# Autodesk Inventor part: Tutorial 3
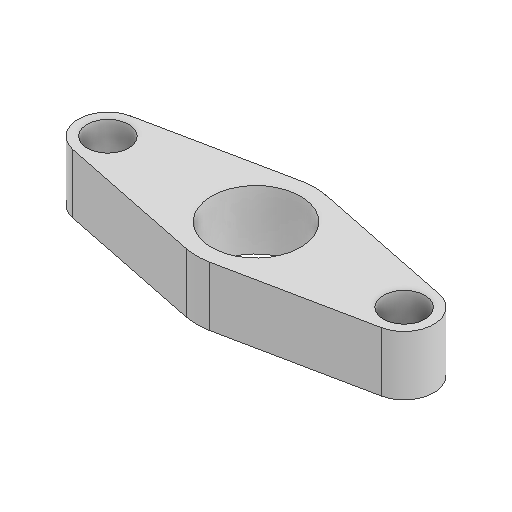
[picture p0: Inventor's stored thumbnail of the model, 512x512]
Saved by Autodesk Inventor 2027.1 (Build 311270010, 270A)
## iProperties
Created: 2021-04
Part Number: Tutorial 3
Material: Generic
Document SubType Name: Modeling
Designer: ASUS Laptop
Density: 1 g/cm^3
Appearance: Default
Author: ASUS Laptop
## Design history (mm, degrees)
sketch "Sketch1"
  geometry: L1 (26, -4.899)-(2, -9.798); L2 (-26, -4.899)-(-2, -9.798); L3 (-26, 4.899)-(-2, 9.798); L4 (26, 4.899)-(2, 9.798); L5 (0, 0)-(-33.69, 0); L6 (0, 0)-(0, -33.352); C1 r 7.5 at (0, 0); C2 r 3.5 at (25, 0); C3 r 3.5 at (-25, 0); A1 r 5 centre (-25, 0) between (-26, 4.899) and (-26, -4.899); A2 r 5 centre (25, 0) between (26, -4.899) and (26, 4.899); A3 r 10 centre (0, 0) between (-2, -9.798) and (2, -9.798); A4 r 10 centre (0, 0) between (2, 9.798) and (-2, 9.798); 1 further point
  constraints: 12 end point, 8 point on circle, 8 tangent, 7 centre point, 4 coincident, 2 equal radius, 2 point on line, 1 horizontal, 1 vertical, 2 other
  dimensions: "d0" = 10 radius of A3; "d1" = 5 radius of A2; "d2" = 50 distance of A1.centre A2.centre; "d3" = 7 diameter of C2; "d4" = 15 diameter of C1
extrude "Extrusion1" new body sketch "Sketch1" distance "d5" = 10; taper "d6" = 0 deg
body "Solid1"
